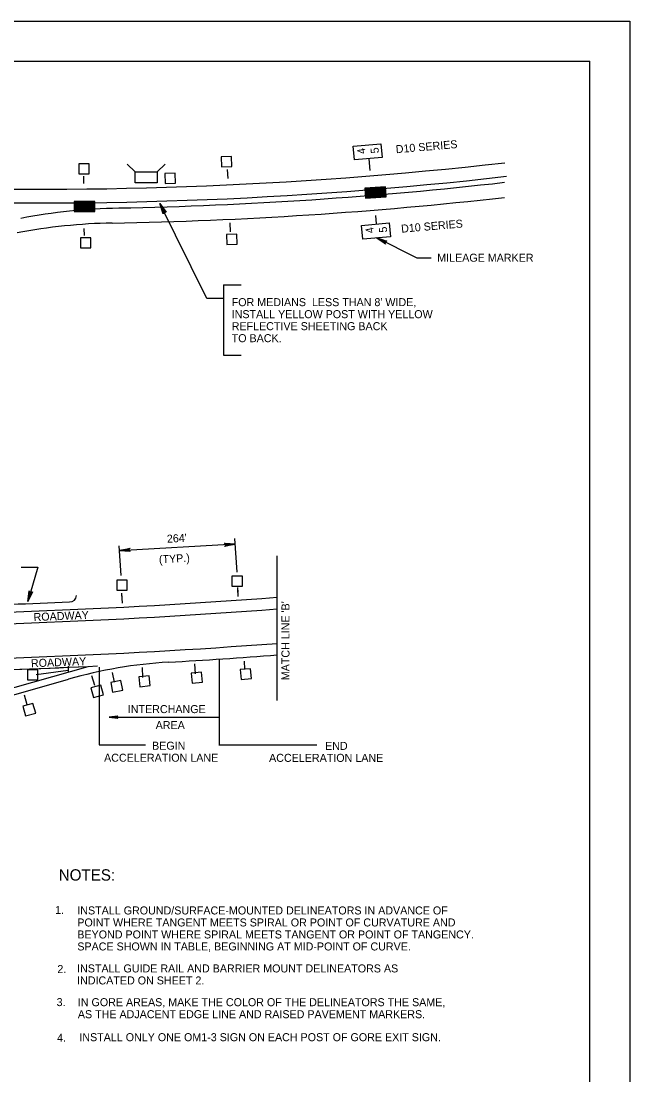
# Model space of a CAD drawing. Extents: x 640253 to 641999, y 298458 to 299646.
# Drawn here: x 641707.1 to 641935.3, y 299250.5 to 299645.6 of the extents above; entities that cross this region are included whole.
import ezdxf

# ---------------------------------------------------------------- set-up
doc = ezdxf.new("R2010")
doc.units = 0
for name, color, linetype in [('1', 7, 'Continuous'), ('2', 7, 'Continuous'), ('PLT-BNDY', 7, 'Continuous')]:
    doc.layers.add(name, color=color, linetype=linetype)

msp = doc.modelspace()

# ---------------------------------------------------------------- linework, layer by layer
at = {"layer": '1'}
for p in [(641134.31, 299630.63), (641920.31, 299066.63)]:
    msp.add_line(p, (641920.31, 299630.63), dxfattribs=at)
at = {"layer": '2'}
for p, q in [((641749.79, 299589.1), (641746.85, 299592.04)), ((641758.12, 299589.1), (641761.06, 299592.04)), ((641837.89, 299589.6), (641837.54, 299594.04)), ((641730.6, 299584.77), (641730.59, 299587.43)), ((641784.66, 299586.64), (641784.49, 299590.04)), ((641840.27, 299569.56), (641840.02, 299572.73)), ((641730.82, 299565.25), (641730.79, 299567.92)), ((641785.59, 299566.63), (641785.43, 299570.02)), ((641782.99, 299546.75), (641789.62, 299546.75)), ((641782.99, 299546.75), (641782.99, 299520.41)), ((641782.99, 299520.41), (641789.62, 299520.41)), ((641744.54, 299437.76), (641743.89, 299448.92)), ((641787.38, 299449.54), (641744, 299446.98)), ((641788.1, 299439.07), (641787.2, 299451.66)), ((641803.08, 299390.85), (641803.08, 299445.17)), ((641707.16, 299440.83), (641713.41, 299440.83)), ((641713.41, 299440.83), (641709.61, 299428.01)), ((641788.5, 299429.87), (641788.3, 299432.76)), ((641788.42, 299431.48), (641788.31, 299433.25)), ((641745.08, 299427.35), (641744.89, 299431.15)), ((641744.99, 299428.96), (641744.89, 299430.73)), ((641772.43, 299400.9), (641772.24, 299404.7)), ((641781.29, 299406.17), (641781.29, 299374.22)), ((641791.02, 299402.7), (641790.81, 299405.6)), ((641589.09, 299362.8), (641732.18, 299403.67)), ((641712.74, 299400.65), (641724.72, 299402.27)), ((641724.87, 299401.52), (641724.87, 299403.72)), ((641736.33, 299403.34), (641736.33, 299374.22)), ((641741.21, 299401.43), (641741.92, 299397.81)), ((641752.77, 299399.47), (641752.58, 299403.27)), ((641593.29, 299361.29), (641724.82, 299398.87)), ((641733.54, 299400.24), (641734.58, 299396.61)), ((641708.19, 299393), (641709.24, 299389.37)), ((641740.07, 299384.62), (641781.29, 299384.62)), ((641736.33, 299374.22), (641753.7, 299374.22)), ((641781.17, 299374.22), (641817.92, 299374.22))]:
    msp.add_line(p, q, dxfattribs=at)
for points in [[(641832.07, 299593.57), (641831.62, 299598.75), (641842, 299599.65), (641842.45, 299594.47)], [(641782.22, 299591), (641786.11, 299591.14), (641785.98, 299594.88), (641782.09, 299594.75)], [(641728.69, 299588.38), (641732.59, 299588.38), (641732.59, 299592.13), (641728.69, 299592.13)], [(641749.79, 299584.93), (641749.79, 299589.1), (641758.12, 299589.1), (641758.12, 299584.93)], [(641761.13, 299584.75), (641765.02, 299584.89), (641764.89, 299588.63), (641761, 299588.49)], [(641835.19, 299563.86), (641834.74, 299569.04), (641845.12, 299569.94), (641845.57, 299564.76)], [(641729.32, 299560.61), (641733.21, 299560.61), (641733.21, 299564.36), (641729.32, 299564.36)], [(641784.23, 299561.88), (641788.12, 299562.01), (641787.99, 299565.76), (641784.1, 299565.62)], [(641786.14, 299433.82), (641790.04, 299433.82), (641790.04, 299437.57), (641786.14, 299437.57)], [(641742.99, 299432.2), (641746.89, 299432.2), (641746.89, 299435.95), (641742.99, 299435.95)], [(641709.51, 299398.7), (641713.41, 299398.7), (641713.41, 299402.45), (641709.51, 299402.45)], [(641771.2, 299397.43), (641775.08, 299397.77), (641774.75, 299401.51), (641770.87, 299401.17)], [(641789.56, 299398.75), (641793.45, 299399.08), (641793.12, 299402.82), (641789.24, 299402.48)], [(641741.41, 299394), (641745.23, 299394.75), (641744.52, 299398.42), (641740.7, 299397.68)], [(641751.56, 299396.06), (641755.44, 299396.46), (641755.05, 299400.19), (641751.18, 299399.78)], [(641734.21, 299391.99), (641737.96, 299393.06), (641736.93, 299396.66), (641733.18, 299395.59)], [(641708.8, 299385.13), (641712.55, 299386.2), (641711.52, 299389.8), (641707.77, 299388.73)]]:
    msp.add_lwpolyline(points, close=True, dxfattribs=at)
for points in [[(641836.14, 299579.19), (641840.03, 299579.46), (641839.77, 299583.2), (641835.88, 299582.92), (641836.14, 299579.19), (641839.71, 299583.12), (641835.95, 299582.86), (641836.2, 299579.24), (641839.96, 299579.51), (641839.72, 299583.06), (641836.03, 299582.8), (641836.27, 299579.31), (641839.88, 299579.57), (641839.63, 299582.96), (641836.1, 299582.71), (641836.34, 299579.38), (641839.81, 299579.62), (641839.58, 299582.9), (641836.18, 299582.66), (641836.4, 299579.44), (641839.73, 299579.68), (641839.5, 299582.82), (641836.25, 299582.6), (641836.46, 299579.5), (641839.66, 299579.75), (641839.42, 299582.74), (641836.33, 299582.53), (641836.52, 299579.57), (641839.58, 299579.81), (641839.36, 299582.67), (641836.4, 299582.46), (641836.57, 299579.66), (641839.49, 299579.89), (641839.3, 299582.58), (641836.49, 299582.39), (641836.64, 299579.71), (641839.38, 299579.95), (641839.22, 299582.51), (641836.57, 299582.33), (641836.71, 299579.78), (641839.3, 299580.01), (641839.13, 299582.45), (641836.66, 299582.25), (641836.79, 299579.83), (641839.21, 299580.07), (641839.04, 299582.36), (641836.75, 299582.17), (641836.78, 299581.07), (641836.86, 299579.91), (641839.13, 299580.14), (641838.95, 299582.26), (641836.84, 299582.07), (641836.94, 299579.99), (641839.04, 299580.2), (641838.87, 299582.17), (641836.95, 299581.98), (641837.04, 299580.08), (641838.91, 299580.26), (641838.76, 299582.04), (641837.09, 299581.88), (641837.15, 299580.22), (641838.75, 299580.36), (641838.62, 299581.92), (641837.26, 299581.77), (641837.28, 299580.34), (641837.29, 299580.34), (641838.6, 299580.49), (641838.5, 299581.77), (641837.4, 299581.65), (641837.42, 299580.48), (641838.43, 299580.61), (641838.37, 299581.6), (641837.55, 299581.53), (641837.57, 299580.65), (641838.27, 299580.73), (641838.19, 299581.46), (641837.72, 299581.4), (641837.75, 299580.8), (641838.08, 299580.85), (641838.05, 299581.3), (641837.91, 299581.31), (641837.91, 299580.95)], [(641840.07, 299579.5), (641843.97, 299579.77), (641843.7, 299583.51), (641839.81, 299583.24), (641840.07, 299579.5), (641843.64, 299583.44), (641839.88, 299583.17), (641840.14, 299579.56), (641843.9, 299579.82), (641843.65, 299583.37), (641839.97, 299583.11), (641840.21, 299579.63), (641843.82, 299579.89), (641843.57, 299583.28), (641840.04, 299583.03), (641840.27, 299579.7), (641843.74, 299579.94), (641843.52, 299583.21), (641840.11, 299582.98), (641840.34, 299579.76), (641843.66, 299580), (641843.43, 299583.14), (641840.18, 299582.91), (641840.39, 299579.82), (641843.59, 299580.06), (641843.36, 299583.06), (641840.26, 299582.84), (641840.45, 299579.89), (641843.52, 299580.13), (641843.3, 299582.99), (641840.33, 299582.78), (641840.51, 299579.97), (641843.42, 299580.2), (641843.23, 299582.89), (641840.43, 299582.71), (641840.57, 299580.03), (641843.32, 299580.27), (641843.15, 299582.83), (641840.51, 299582.64), (641840.64, 299580.1), (641843.24, 299580.32), (641843.07, 299582.76), (641840.59, 299582.57), (641840.72, 299580.15), (641843.14, 299580.39), (641842.98, 299582.68), (641840.68, 299582.49), (641840.71, 299581.39), (641840.79, 299580.22), (641843.06, 299580.46), (641842.88, 299582.57), (641840.77, 299582.39), (641840.87, 299580.3), (641842.97, 299580.52), (641842.8, 299582.49), (641840.88, 299582.3), (641840.98, 299580.4), (641842.84, 299580.58), (641842.7, 299582.35), (641841.03, 299582.2), (641841.08, 299580.53), (641842.69, 299580.67), (641842.56, 299582.24), (641841.19, 299582.09), (641841.21, 299580.66), (641841.22, 299580.66), (641842.53, 299580.8), (641842.43, 299582.08), (641841.33, 299581.97), (641841.35, 299580.8), (641842.37, 299580.93), (641842.31, 299581.92), (641841.48, 299581.84), (641841.5, 299580.96), (641842.2, 299581.04), (641842.12, 299581.78), (641841.66, 299581.72), (641841.68, 299581.11), (641842.02, 299581.17), (641841.99, 299581.61), (641841.84, 299581.63), (641841.84, 299581.27)], [(641726.93, 299574.27), (641730.83, 299574.27), (641730.83, 299578.01), (641726.93, 299578.01), (641726.93, 299574.27), (641730.77, 299577.94), (641727, 299577.94), (641727, 299574.32), (641730.77, 299574.32), (641730.77, 299577.88), (641727.07, 299577.88), (641727.07, 299574.39), (641730.69, 299574.39), (641730.68, 299577.79), (641727.14, 299577.79), (641727.14, 299574.44), (641730.62, 299574.44), (641730.62, 299577.73), (641727.21, 299577.73), (641727.21, 299574.5), (641730.54, 299574.51), (641730.53, 299577.66), (641727.28, 299577.66), (641727.27, 299574.56), (641730.48, 299574.58), (641730.46, 299577.59), (641727.35, 299577.59), (641727.34, 299574.63), (641730.41, 299574.65), (641730.39, 299577.52), (641727.42, 299577.52), (641727.4, 299574.71), (641730.32, 299574.73), (641730.32, 299577.42), (641727.51, 299577.44), (641727.47, 299574.75), (641730.22, 299574.8), (641730.23, 299577.37), (641727.58, 299577.37), (641727.54, 299574.82), (641730.14, 299574.86), (641730.14, 299577.31), (641727.66, 299577.29), (641727.62, 299574.86), (641730.06, 299574.93), (641730.05, 299577.23), (641727.75, 299577.2), (641727.7, 299576.1), (641727.7, 299574.93), (641729.98, 299575.01), (641729.95, 299577.13), (641727.83, 299577.1), (641727.79, 299575.01), (641729.89, 299575.08), (641729.86, 299577.06), (641727.93, 299577), (641727.89, 299575.1), (641729.76, 299575.14), (641729.75, 299576.93), (641728.07, 299576.89), (641728.01, 299575.22), (641729.62, 299575.25), (641729.6, 299576.82), (641728.22, 299576.76), (641728.15, 299575.34), (641728.16, 299575.34), (641729.47, 299575.39), (641729.46, 299576.67), (641728.36, 299576.64), (641728.29, 299575.47), (641729.32, 299575.53), (641729.32, 299576.52), (641728.5, 299576.5), (641728.46, 299575.62), (641729.16, 299575.65), (641729.13, 299576.39), (641728.67, 299576.36), (641728.64, 299575.76), (641728.99, 299575.79), (641728.99, 299576.24), (641728.84, 299576.27), (641728.82, 299575.91)], [(641730.87, 299574.27), (641734.77, 299574.27), (641734.77, 299578.01), (641730.87, 299578.01), (641730.87, 299574.27), (641734.7, 299577.94), (641730.93, 299577.94), (641730.93, 299574.32), (641734.7, 299574.32), (641734.7, 299577.88), (641731.01, 299577.88), (641731.01, 299574.39), (641734.62, 299574.39), (641734.62, 299577.79), (641731.08, 299577.79), (641731.08, 299574.44), (641734.56, 299574.44), (641734.56, 299577.73), (641731.15, 299577.73), (641731.15, 299574.5), (641734.48, 299574.51), (641734.47, 299577.66), (641731.21, 299577.66), (641731.2, 299574.56), (641734.41, 299574.58), (641734.39, 299577.59), (641731.28, 299577.59), (641731.27, 299574.63), (641734.34, 299574.65), (641734.32, 299577.52), (641731.35, 299577.52), (641731.33, 299574.71), (641734.26, 299574.73), (641734.26, 299577.42), (641731.44, 299577.44), (641731.4, 299574.75), (641734.16, 299574.81), (641734.17, 299577.37), (641731.52, 299577.37), (641731.48, 299574.82), (641734.08, 299574.86), (641734.08, 299577.31), (641731.59, 299577.29), (641731.56, 299574.86), (641733.99, 299574.93), (641733.98, 299577.23), (641731.68, 299577.2), (641731.63, 299576.1), (641731.63, 299574.93), (641733.91, 299575.01), (641733.88, 299577.14), (641731.76, 299577.1), (641731.72, 299575.01), (641733.83, 299575.08), (641733.8, 299577.06), (641731.87, 299577), (641731.83, 299575.1), (641733.7, 299575.14), (641733.68, 299576.93), (641732, 299576.89), (641731.95, 299575.22), (641733.55, 299575.25), (641733.53, 299576.82), (641732.16, 299576.76), (641732.08, 299575.34), (641732.09, 299575.34), (641733.41, 299575.39), (641733.4, 299576.68), (641732.29, 299576.64), (641732.23, 299575.47), (641733.25, 299575.53), (641733.26, 299576.52), (641732.43, 299576.5), (641732.39, 299575.62), (641733.09, 299575.65), (641733.07, 299576.39), (641732.6, 299576.36), (641732.58, 299575.76), (641732.92, 299575.79), (641732.92, 299576.24), (641732.77, 299576.27), (641732.75, 299575.91)], [(641782.99, 299541.63), (641776.74, 299541.63), (641759.14, 299577.21)], [(641760.39, 299573.6), (641760.58, 299573.85), (641759.14, 299577.21), (641760.39, 299573.6), (641760.33, 299573.35), (641759.14, 299577.21), (641760.91, 299574.02), (641761.22, 299574.02), (641759.14, 299577.21), (641761.47, 299573.92), (641761.22, 299574.02)], [(641860.81, 299556.75), (641855.6, 299556.75), (641840.38, 299564.31)], [(641843.57, 299562.22), (641843.54, 299562.52), (641840.38, 299564.31), (641843.57, 299562.22), (641843.65, 299561.99), (641840.38, 299564.31), (641843.72, 299562.86), (641843.96, 299563.05), (641840.38, 299564.31), (641844.21, 299563.12), (641843.96, 299563.05)], [(641783.57, 299449.79), (641783.73, 299449.52), (641787.38, 299449.54), (641783.57, 299449.79), (641783.37, 299449.94), (641787.38, 299449.54), (641783.75, 299449.14), (641783.64, 299448.87), (641787.38, 299449.54), (641783.44, 299448.67), (641783.64, 299448.87)], [(641747.81, 299446.87), (641747.65, 299447.14), (641744, 299447.12), (641747.81, 299446.87), (641748.01, 299446.72), (641744, 299447.12), (641747.62, 299447.52), (641747.74, 299447.8), (641744, 299447.12), (641747.93, 299447.99), (641747.74, 299447.8)], [(641711.14, 299431.51), (641710.84, 299431.45), (641709.61, 299428.01), (641711.14, 299431.51), (641711.35, 299431.65), (641709.61, 299428.01), (641710.47, 299431.56), (641710.25, 299431.76), (641709.61, 299428.01), (641710.13, 299432.01), (641710.25, 299431.76)], [(641743.22, 299384.23), (641743.1, 299384.45), (641740.07, 299384.62), (641743.22, 299384.23), (641743.38, 299384.09), (641740.07, 299384.62), (641743.1, 299384.78), (641743.21, 299385.01), (641740.07, 299384.62), (641743.38, 299385.15), (641743.21, 299385.01)]]:
    msp.add_lwpolyline(points, dxfattribs=at)
for centre, radius, start, end in [((641713.53, 301122.08), 1539.51, 267.61256, 276.52429), ((641713.53, 301122.08), 1544.66, 267.61256, 276.52429), ((641713.53, 301122.08), 1546.82, 271.11716, 276.48929), ((641713.53, 301122.08), 1552.43, 271.024, 276.46547), ((641747.52, 299361.36), 214.14, 91.0236, 100.9066), ((641745, 299361.65), 208.29, 91.0236, 100.9066), ((641618.76, 301866.5), 2443.88, 270.0023, 274.32557), ((641725.38, 299430.4), 2.53, 267.2199, 357.1395), ((641618.76, 301866.5), 2448.22, 270.0023, 274.31789), ((641617.17, 301869.36), 2443.88, 271.50321, 272.53479), ((641618.76, 301866.5), 2461.1, 270.0023, 274.29526), ((641772.51, 299231.98), 173.57, 93.3401, 105.9471), ((641618.76, 301866.5), 2465.44, 273.34006, 274.28767), ((641618.76, 301866.5), 2465.44, 270.0023, 272.72047), ((641618.76, 301866.5), 2465.43, 270.0023, 272.63682)]:
    msp.add_arc(centre, radius, start, end, dxfattribs=at)
at = {"layer": 'PLT-BNDY'}
msp.add_lwpolyline([(641094.31, 299645.63), (641935.31, 299645.63), (641935.31, 299051.63), (641094.31, 299051.63)], close=True, dxfattribs=at)

# ---------------------------------------------------------------- texts
at = {"layer": '2'}
for s, rotation, p in [('D10 SERIES', 4.9285, (641847.66, 299596.06)), ('4', 99.9017, (641836.32, 299596.04)), ('5', 94.9302, (641841.23, 299596.14)), ('D10 SERIES', 4.9285, (641849.68, 299566.27)), ('4', 99.9017, (641839.43, 299566.33)), ('5', 94.9302, (641844.34, 299566.43)), ("264'", 3.3665, (641761.83, 299450.02)), ('(TYP.)', 3.3665, (641758.84, 299442.26)), ('ROADWAY', 2.3651, (641711.82, 299420.65)), ("MATCH LINE 'B'", 90, (641807.7, 299398.49)), ('ROADWAY', 2.3651, (641710.85, 299403.33))]:
    msp.add_text(s, height=3, rotation=rotation, dxfattribs=at).set_placement(p)
for s, height, p in [('MILEAGE MARKER', 3, (641863.08, 299555.4)), ("FOR MEDIANS  LESS THAN 8' WIDE,", 3, (641786.03, 299538.74)), ('INSTALL YELLOW POST WITH YELLOW', 3, (641786.03, 299534.24)), ('REFLECTIVE SHEETING BACK ', 3, (641786.03, 299529.74)), ('TO BACK.', 3, (641786.03, 299525.24)), ('INTERCHANGE', 3, (641747.09, 299386.17)), ('AREA', 3, (641757.53, 299380.17)), ('BEGIN', 3, (641756.18, 299372.44)), ('END', 3, (641821.04, 299372.39)), ('ACCELERATION LANE', 3, (641738.19, 299367.94)), ('ACCELERATION LANE', 3, (641800.05, 299367.89)), ('NOTES:', 4.25, (641721.19, 299323.37)), ('1. ', 3, (641719.85, 299310.86)), ('INSTALL GROUND/SURFACE-MOUNTED DELINEATORS IN ADVANCE OF', 3, (641728.16, 299310.68)), ('POINT WHERE TANGENT MEETS SPIRAL OR POINT OF CURVATURE AND', 3, (641728.16, 299306.18)), ('BEYOND POINT WHERE SPIRAL MEETS TANGENT OR POINT OF TANGENCY.', 3, (641728.16, 299301.68)), ('SPACE SHOWN IN TABLE, BEGINNING AT MID-POINT OF CURVE.', 3, (641728.16, 299297.18)), ('2. ', 3, (641720.67, 299288.7)), ('INSTALL GUIDE RAIL AND BARRIER MOUNT DELINEATORS AS', 3, (641728.08, 299288.94)), ('INDICATED ON SHEET 2.', 3, (641728.08, 299284.44)), ('3. ', 3, (641720.4, 299276.32)), ('IN GORE AREAS, MAKE THE COLOR OF THE DELINEATORS THE SAME,', 3, (641728.36, 299276.28)), ('AS THE ADJACENT EDGE LINE AND RAISED PAVEMENT MARKERS.', 3, (641728.36, 299271.78)), ('4. ', 3, (641720.59, 299262.97)), ('INSTALL ONLY ONE OM1-3 SIGN ON EACH POST OF GORE EXIT SIGN.', 3, (641728.92, 299263.16))]:
    msp.add_text(s, height=height, dxfattribs=at).set_placement(p)

doc.saveas('drawing.dxf')
